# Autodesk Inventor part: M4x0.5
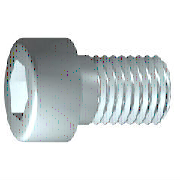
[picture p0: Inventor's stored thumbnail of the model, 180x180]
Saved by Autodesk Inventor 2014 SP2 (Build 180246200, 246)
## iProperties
IsCustomPart: 1
Company: 한국ATC센터
Created: 2014-11
Part Number: M4x0.5
Material: 강, 연강
Description: 6각머리 태핑 나사
Document SubType Name: Modeling
Standard: KS B 1003
Designer: KYOUNG IL JANG
Standards Organization: KS
Language: ko-KR
Size Designation: M 4 x 16
Categories: <MemberInstance><Categories><Category DisplayName="조임쇠" InternalName="e4da775c-781d-43d5-af7c-5136215cf5a6" Mnemonic="FSTN"><Category DisplayName="볼트" InternalN
Density: 7.86 g/cm^3
Mass: 2.62973 g
Surface Area: 3.81119 cm^2
Volume: 0.334572 cm^3
Appearance: 강철
Author: KYOUNG IL JANG
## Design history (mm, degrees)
sketch "스케치1"
  geometry: L1 (-1, 0)-(16, 0); L2 (16, 0)-(16, 2); L3 (16, 2)-(1.75, 2); L4 (1.75, 2)-(1.32, 2); L5 (1.32, 2)-(0, 2); L6 (0, 2)-(0, 3.5); L7 (0, 3.5)-(-4, 3.5); L8 (-4, 3.5)-(-4, 1.732); L9 (-4, 1.732)-(-2, 1.732); L10 (-2, 1.732)-(-1, 0); L11 (-8, 0)-(20, 0) reference; L12 (0, -0.7)-(0, 4.2) reference; L13 (1.75, 2)-(0, 2)
  constraints: 22 end point, 6 parallel, 2 collinear, 2 perpendicular, 1 horizontal, 1 point on line
  dimensions: "d1" = 14.25 distance from line of L3.end L2 (= GEL); "d2" = 0.42952 distance of L4.end L3.end (computed from GAL); "d3" = 4 distance between parallel lines of L8 L6 (= KOH); "d4" = 2 distance of L8.end L9.end (= INTI); "d5" = 60 deg angle of L10 L1; "d6" = 4 diameter of L3 L1 (= GD); "d7" = 4 diameter of L5 L1 (= BDM); "d8" = 3.4641 diameter of L9 L1 (= 1.1547 x SW); "d9" = 7 diameter of L7 L1 (= KOD); "d26" = 16 distance between parallel lines of L12 L2 (= NLG)
revolve "본체" sketch "스케치1" stored, may be unused: angle "d10" = 90 deg
sketch "스케치2"
  geometry: L1 (0, -4.9)-(0, 4.9) reference; L2 (-4.9, 0)-(4.9, 0) reference; L3 (1.732, 0)-(0.866, -1.5); L4 (0.866, -1.5)-(-0.866, -1.5); L5 (-0.866, -1.5)-(-1.732, 0); L6 (-1.732, 0)-(-0.866, 1.5); L7 (-0.866, 1.5)-(0.866, 1.5); L8 (0.866, 1.5)-(1.732, 0); 2 further points
  constraints: 12 end point, 1 coincident, 1 horizontal alignment, 1 point on line, 12 other
extrude "슬롯" join sketch "스케치2" stored distance "d11" = 10; taper "d12" = 0 deg
workplane "Work Plane1"
fillet "Fillet2" dims "d30" = 0.1 (= R)
body "Solid1"
fillet "모깎기1" dims "d17" = 0.4 (= RR)
feature "스레드" dims "d13" = 14.25 (= GEL), "d14" = 0
chamfer "모따기1" distance "d15" = 0.42941 (= -0.5 x SPD + 0.5 x GD); stored, may be unused: second distance "d16" = 0.42941 (= GUL), angle "d27" = 45 deg
other parameters: "GD" = 4 (= NND) [user parameter; used in 2 equation terms], "NLG" = 16 [user parameter; used in 1 equation term], "GEL" = 14.25 [user parameter; used in 2 equation terms], "KOD" = 7 [user parameter; used in 1 equation term], "KOH" = 4 [user parameter; used in 1 equation term], "INTI" = 2 [user parameter; used in 1 equation term], "GAL" = 0.42941 (= 0.61345 x PTC) [user parameter; used in 1 equation term], "GUL" = 0.42941 (= 0.61345 x PTC) [user parameter; used in 1 equation term], "BDM" = 4 (= NND) [user parameter; used in 1 equation term], "SW" = 3 [user parameter; used in 2 equation terms], "RR" = 0.4 [user parameter; used in 1 equation term], "SPD" = 3.14117 (= NND - 1.2269 x PTC) [user parameter; used in 1 equation term], "d19" = 0, "d28" = 0, "d29" = 0, "R" = 0.1 [user parameter; used in 1 equation term], "PHH" = 0.2 [user parameter], "GD1" = 3.14117 (= THREADDIA - 1.2269 x PTC) [user parameter], "THREADDIA" = 4 [user parameter; used in 1 equation term], "FAWI" = 45 deg [user parameter], "TPU" = 14.28571 (computed from PTC) [user parameter], "PTC" = 0.7 [user parameter; used in 5 equation terms], "NND" = 4 [user parameter; used in 3 equation terms], "TOA" = 30 deg [user parameter], "E0" = 3.465 (= 1.155 x SW) [user parameter]
